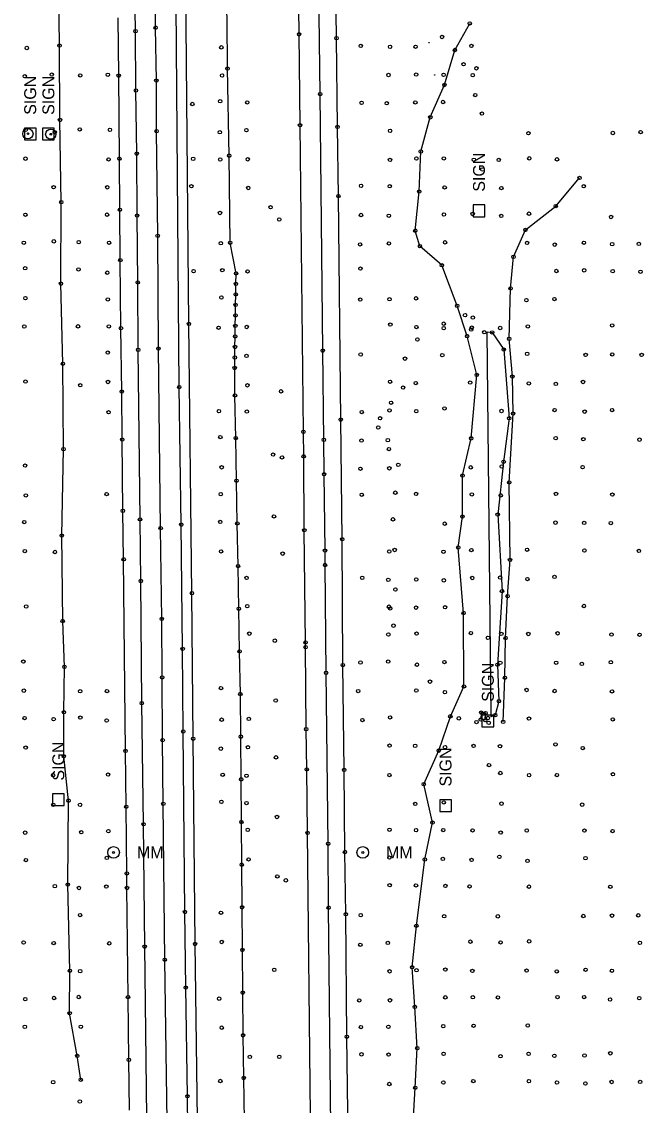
# Model space of a CAD drawing. Extents: x 20503438 to 20508873, y 7964251 to 7984667.
# Drawn here: x 20505333 to 20505698, y 7979935 to 7980570 of the extents above; entities that cross this region are included whole.
import ezdxf

# ---------------------------------------------------------------- set-up
doc = ezdxf.new("R2010")
doc.units = 0
for name, color, linetype in [('SurBreakLine', 7, 'Continuous'), ('SurControl', 7, 'Continuous'), ('SurDrainageArrowDown', 7, 'Continuous'), ('SurEdgeRoadPaved', 7, 'Continuous'), ('SurEdgeShoulderPaved', 7, 'Continuous'), ('SurMiscStructureLine', 7, 'Continuous'), ('SurPointsNonDTM', 7, 'Continuous'), ('SurRoadPoints', 7, 'Continuous'), ('SurSurveyPoints', 7, 'Continuous'), ('SurTreeLineLeft', 7, 'Continuous')]:
    doc.layers.add(name, color=color, linetype=linetype)

msp = doc.modelspace()

# ---------------------------------------------------------------- linework, layer by layer
at = {"layer": 'SurBreakLine'}
for points in [[(20505502.82, 7979928.73), (20505501.16, 7980094.42), (20505500.7, 7980131.63), (20505500.35, 7980155.21), (20505500.03, 7980203.28), (20505500, 7980206.06), (20505499.27, 7980271.76), (20505498.89, 7980315.07), (20505498.72, 7980329.42), (20505496.74, 7980509.09), (20505496.18, 7980562.37), (20505495.83, 7980592.98), (20505495.56, 7980624.79), (20505494.56, 7980715.32), (20505494.07, 7980758.55), (20505493.65, 7980795.75), (20505493.28, 7980832.76), (20505492.74, 7980874.49), (20505492.33, 7980901.35), (20505491.27, 7980994.69)], [(20505418.93, 7979912.11), (20505417.39, 7980020.09), (20505416.54, 7980111.44), (20505416.16, 7980148.77), (20505415.87, 7980185.54), (20505415.61, 7980219.83), (20505414.98, 7980273.06), (20505413.7, 7980378.2), (20505413.25, 7980444.28), (20505412.62, 7980505.63), (20505412.46, 7980535.27), (20505412.01, 7980566.27), (20505411.1, 7980668.83), (20505409.87, 7980764.66), (20505409.52, 7980790.7), (20505409.02, 7980836.41), (20505408.56, 7980861.54), (20505408.11, 7980905.42), (20505407.63, 7980936.71)], [(20505615.91, 7980159.52), (20505616.95, 7980185.34), (20505617.35, 7980208.62), (20505618.51, 7980233.14), (20505619.93, 7980254.39), (20505619.47, 7980299.79), (20505621.75, 7980340.13), (20505621.29, 7980361.79), (20505619.43, 7980383.94), (20505620.25, 7980413.47), (20505621.95, 7980432), (20505628.98, 7980447.77), (20505646.74, 7980461.72), (20505660.76, 7980478.21)]]:
    msp.add_lwpolyline(points, dxfattribs=at)
at = {"layer": 'SurControl'}
for centre in [(20505572.47, 7980557.49), (20505575.81, 7980538.5)]:
    msp.add_circle(centre, 0.15, dxfattribs=at)
at = {"layer": 'SurDrainageArrowDown'}
for points in [[(20505455.75, 7980440.25), (20505455.16, 7980491.26), (20505454.21, 7980542.27), (20505454.01, 7980570.91), (20505453.19, 7980592.26), (20505451.34, 7980609.26), (20505446.96, 7980613.69), (20505442.6, 7980613.8)], [(20505368.13, 7979949.77), (20505366.04, 7979963.72), (20505361.61, 7979988.72), (20505361.78, 7980013.67), (20505360.5, 7980064.12), (20505360.95, 7980113.29), (20505358.15, 7980139.35), (20505358.26, 7980165.11), (20505358.56, 7980191.72), (20505357.53, 7980218.57), (20505356.98, 7980268.66), (20505358, 7980319.29), (20505357.64, 7980369.33), (20505356.48, 7980416.28), (20505356.69, 7980464.03), (20505355.94, 7980512.18), (20505355.65, 7980555.76), (20505355.07, 7980601.84)], [(20505563.12, 7979924.54), (20505564.34, 7979945.1), (20505565.51, 7979968.29), (20505564.11, 7979992.43), (20505562.47, 7980015.69), (20505564.99, 7980040.01), (20505569.98, 7980078.85), (20505574.44, 7980100.46), (20505569.31, 7980122.96), (20505578.13, 7980142.63), (20505584.92, 7980162.71), (20505592.92, 7980180.26), (20505592.67, 7980223.26), (20505589.56, 7980261.64), (20505591.98, 7980279.78), (20505592.04, 7980303.79), (20505597.14, 7980325.64), (20505600.42, 7980362.8), (20505594.74, 7980385.49), (20505588.92, 7980403.27), (20505579.92, 7980427.03), (20505567.05, 7980438.23), (20505564.34, 7980447.3), (20505566.67, 7980470.22), (20505567.62, 7980493.73), (20505573.17, 7980513.73), (20505581.44, 7980532.68), (20505587.62, 7980553.18), (20505596.29, 7980568.74)], [(20505464.1, 7979925.82), (20505463.72, 7979950.81), (20505463.34, 7979975.81), (20505463.14, 7980000.81), (20505462.95, 7980025.81), (20505462.77, 7980050.81), (20505462.58, 7980075.8), (20505462.39, 7980100.8), (20505462.2, 7980125.8), (20505462.01, 7980150.8), (20505461.74, 7980175.8), (20505461.29, 7980200.79), (20505460.85, 7980225.79), (20505460.4, 7980250.79), (20505459.95, 7980275.78), (20505459.5, 7980300.78), (20505459.05, 7980325.77), (20505458.6, 7980350.77), (20505458.41, 7980366.85), (20505458.5, 7980373.01), (20505458.6, 7980379.17), (20505458.69, 7980385.33), (20505458.78, 7980391.49), (20505458.88, 7980397.65), (20505458.97, 7980403.81), (20505459.06, 7980409.97), (20505459.16, 7980416.13), (20505459.25, 7980422.29), (20505455.75, 7980440.25)]]:
    msp.add_lwpolyline(points, dxfattribs=at)
at = {"layer": 'SurEdgeRoadPaved'}
for points in [[(20505407.01, 7979911.27), (20505405.62, 7980027.77), (20505404.97, 7980099.48), (20505403.88, 7980170.44), (20505403.36, 7980242.05), (20505402.88, 7980278.12), (20505401.81, 7980377.51), (20505401.55, 7980417.01), (20505401.15, 7980456.16), (20505400.97, 7980492.44), (20505400.5, 7980529.47), (20505400.23, 7980564.23), (20505399.63, 7980600.95), (20505398.46, 7980703.6), (20505397.89, 7980772.13), (20505396.33, 7980909.55), (20505395.68, 7980987.14)], [(20505433.05, 7979713.21), (20505430.71, 7979940.08), (20505429.71, 7980003.79), (20505429.2, 7980048.09), (20505428.22, 7980153.85), (20505427.89, 7980202.23), (20505427.07, 7980275.05), (20505425.92, 7980355.65), (20505424.11, 7980579.66), (20505423.37, 7980648.54), (20505420.77, 7980848.98), (20505419.47, 7980988.86)], [(20505516.05, 7979812.06), (20505513.49, 7980050.6), (20505513.24, 7980088.09), (20505512.01, 7980188.2), (20505511.47, 7980251.39), (20505511.41, 7980259.84), (20505510.87, 7980304.58), (20505510.69, 7980324.76), (20505510.08, 7980377.01), (20505508.54, 7980527.34), (20505507.19, 7980635.55), (20505506.92, 7980663.36), (20505505.94, 7980736.75), (20505505.07, 7980842.4), (20505504.2, 7980911.75), (20505503.99, 7980947.26)]]:
    msp.add_lwpolyline(points, dxfattribs=at)
at = {"layer": 'SurEdgeShoulderPaved'}
for points in [[(20505436.58, 7979926.47), (20505435.19, 7980029.33), (20505434.04, 7980149.6), (20505433.33, 7980234.89), (20505431.57, 7980392.66), (20505429.57, 7980611.85), (20505428.94, 7980656.15), (20505428.39, 7980719.4), (20505428.03, 7980745.3), (20505427.42, 7980798.3), (20505426.86, 7980832.89), (20505425.41, 7980977.21)], [(20505525.14, 7979901.72), (20505524.22, 7979974.98), (20505523.61, 7980046.77), (20505523.09, 7980083.23), (20505522.65, 7980131.31), (20505521.87, 7980192.78), (20505521.53, 7980266.52), (20505520.61, 7980336.57), (20505519.29, 7980467.56), (20505518.75, 7980508.1), (20505518.14, 7980560.14), (20505516.98, 7980650.97), (20505516.82, 7980662.74), (20505516.06, 7980714.7), (20505516.27, 7980750.94), (20505515.28, 7980821.55), (20505514.45, 7980923.25)], [(20505396.63, 7979932.02), (20505396.34, 7979961.46), (20505395.84, 7979998.23), (20505395.23, 7980062.14), (20505395.14, 7980070.7), (20505394.81, 7980109.76), (20505394.37, 7980142.46), (20505393.29, 7980254.72), (20505392.82, 7980283.13), (20505392.48, 7980324.91), (20505392.19, 7980353.04), (20505391.71, 7980390.19), (20505391.32, 7980430.1), (20505391.07, 7980459.58), (20505390.82, 7980489.5), (20505390.37, 7980538.15), (20505390.02, 7980571.99)]]:
    msp.add_lwpolyline(points, dxfattribs=at)
at = {"layer": 'SurMiscStructureLine'}
msp.add_lwpolyline([(20505605.38, 7980160.44), (20505605.6, 7980164.63), (20505603.07, 7980164.89), (20505602.78, 7980160.83)], dxfattribs=at)
at = {"layer": 'SurPointsNonDTM'}
for centre in [(20505580.1, 7980560.82), (20505592.68, 7980544.84), (20505600.24, 7980542.46), (20505599.51, 7980526.77), (20505603.43, 7980515.91), (20505603.79, 7980483.17), (20505593.54, 7980397.78), (20505598.1, 7980396.41), (20505581.03, 7980392.8), (20505597.15, 7980389.37), (20505604.79, 7980387.78), (20505609.45, 7980387.7), (20505565.6, 7980383.55), (20505616.27, 7980377.63), (20505558.33, 7980372.32), (20505557.19, 7980355.39), (20505550.18, 7980346.48), (20505543.69, 7980337.38), (20505619.45, 7980337.41), (20505542.61, 7980331.98), (20505548.89, 7980319.31), (20505616.2, 7980311.84), (20505554.41, 7980310.1), (20505552.66, 7980293.77), (20505612.7, 7980280.94), (20505551.3, 7980278.15), (20505552.26, 7980260.2), (20505552.68, 7980237.07), (20505615.23, 7980236.14), (20505549.6, 7980225.94), (20505551.6, 7980215.87), (20505607.01, 7980208.72), (20505612.56, 7980192.97), (20505573.01, 7980183.05), (20505613.39, 7980171.62), (20505589.91, 7980161.55), (20505600.28, 7980159.35), (20505602.78, 7980160.83), (20505603.07, 7980164.89), (20505605.38, 7980160.44), (20505605.6, 7980164.63), (20505606.97, 7980161.77), (20505607.42, 7980158.94), (20505611.29, 7980163.4), (20505607.59, 7980134.15)]:
    msp.add_circle(centre, 1, dxfattribs=at)
at = {"layer": 'SurRoadPoints'}
for points in [[(20505341.89, 7980504.01), (20505341.89, 7980504.01), (20505341.89, 7980507.44), (20505335.03, 7980507.44), (20505335.03, 7980500.58), (20505341.89, 7980500.58), (20505341.89, 7980504.01)], [(20505352.56, 7980503.98), (20505352.56, 7980503.98), (20505352.56, 7980507.41), (20505345.7, 7980507.41), (20505345.7, 7980500.55), (20505352.56, 7980500.55), (20505352.56, 7980503.98)], [(20505605.15, 7980458.95), (20505605.15, 7980458.95), (20505605.15, 7980462.38), (20505598.29, 7980462.38), (20505598.29, 7980455.52), (20505605.15, 7980455.52), (20505605.15, 7980458.95)], [(20505610.35, 7980160.03), (20505610.35, 7980160.03), (20505610.35, 7980163.46), (20505603.49, 7980163.46), (20505603.49, 7980156.6), (20505610.35, 7980156.6), (20505610.35, 7980160.03)], [(20505358.36, 7980113.85), (20505358.36, 7980113.85), (20505358.36, 7980117.28), (20505351.5, 7980117.28), (20505351.5, 7980110.42), (20505358.36, 7980110.42), (20505358.36, 7980113.85)], [(20505585.53, 7980110.41), (20505585.53, 7980110.41), (20505585.53, 7980113.84), (20505578.67, 7980113.84), (20505578.67, 7980106.98), (20505585.53, 7980106.98), (20505585.53, 7980110.41)]]:
    msp.add_lwpolyline(points, dxfattribs=at)
for centre, radius in [((20505337.14, 7980504.13), 3), ((20505337.14, 7980504.13), 0.5), ((20505350.53, 7980503.85), 3), ((20505350.53, 7980503.85), 0.5), ((20505387.38, 7980082.96), 3.43), ((20505533.54, 7980082.96), 3.43), ((20505387.38, 7980082.96), 0.571), ((20505533.54, 7980082.96), 0.571)]:
    msp.add_circle(centre, radius, dxfattribs=at)
at = {"layer": 'SurSurveyPoints'}
for centre in [(20505412.01, 7980566.27), (20505596.29, 7980568.74), (20505400.23, 7980564.23), (20505496.18, 7980562.37), (20505518.14, 7980560.14), (20505336.48, 7980554.35), (20505355.65, 7980555.76), (20505450.58, 7980554.74), (20505532.34, 7980555.56), (20505549.57, 7980555.04), (20505564.55, 7980555.08), (20505587.62, 7980553.18), (20505597.26, 7980555.6), (20505454.21, 7980542.27), (20505335.25, 7980537.8), (20505351.09, 7980538.79), (20505367.81, 7980538.31), (20505384.02, 7980538.69), (20505390.37, 7980538.15), (20505412.46, 7980535.27), (20505451, 7980538.26), (20505548.63, 7980538.55), (20505564.88, 7980538.76), (20505580.97, 7980538.63), (20505598.05, 7980538.44), (20505400.5, 7980529.47), (20505508.54, 7980527.34), (20505581.44, 7980532.68), (20505433.56, 7980521.53), (20505449.89, 7980523.15), (20505465.78, 7980522.45), (20505532.87, 7980522.21), (20505547.64, 7980522), (20505564.37, 7980522.48), (20505580.66, 7980522.71), (20505355.94, 7980512.18), (20505496.74, 7980509.09), (20505518.75, 7980508.1), (20505573.17, 7980513.73), (20505335.79, 7980506.4), (20505352.85, 7980505), (20505367.53, 7980506.65), (20505385.21, 7980506.42), (20505412.62, 7980505.63), (20505449.71, 7980505.01), (20505465.32, 7980506.19), (20505549.59, 7980505.81), (20505630.74, 7980504.4), (20505680.24, 7980504.54), (20505696.56, 7980505.09), (20505335.69, 7980489.49), (20505384.44, 7980489.07), (20505390.82, 7980489.5), (20505400.97, 7980492.44), (20505434.05, 7980489.41), (20505449.95, 7980489), (20505455.16, 7980491.26), (20505466.09, 7980489.14), (20505565.03, 7980489.61), (20505567.62, 7980493.73), (20505581.1, 7980489.65), (20505631.22, 7980489.7), (20505647.5, 7980489.11), (20505549.53, 7980488.75), (20505598.7, 7980488.87), (20505613.3, 7980488.75), (20505660.76, 7980478.21), (20505352.22, 7980472.74), (20505383.65, 7980472.71), (20505432.99, 7980473.36), (20505466.37, 7980472.33), (20505532.58, 7980473.57), (20505549.39, 7980473.37), (20505566.67, 7980470.22), (20505581.58, 7980472.68), (20505614.84, 7980472.29), (20505663.16, 7980473.32), (20505356.69, 7980464.03), (20505519.29, 7980467.56), (20505391.07, 7980459.58), (20505449.81, 7980457.67), (20505479.47, 7980461.05), (20505631.04, 7980457.27), (20505646.74, 7980461.72), (20505335.65, 7980456.62), (20505383.56, 7980456.69), (20505401.15, 7980456.16), (20505484.57, 7980453.84), (20505532.51, 7980456.48), (20505548.82, 7980456.06), (20505581.16, 7980456.77), (20505598.03, 7980457.1), (20505614.81, 7980455.98), (20505679.2, 7980455.34), (20505564.34, 7980447.3), (20505628.98, 7980447.77), (20505334.75, 7980440.25), (20505352.31, 7980441.06), (20505366.96, 7980440.56), (20505384.72, 7980440.23), (20505413.25, 7980444.28), (20505450.28, 7980439.95), (20505455.75, 7980440.25), (20505455.75, 7980440.25), (20505531.99, 7980439.26), (20505548.9, 7980439.85), (20505567.05, 7980438.23), (20505581.82, 7980440.47), (20505629.93, 7980440.16), (20505646.19, 7980439.13), (20505663.3, 7980440.25), (20505679.87, 7980439.42), (20505695.5, 7980439.56), (20505621.95, 7980432), (20505391.32, 7980430.1), (20505579.92, 7980427.03), (20505335.53, 7980425.28), (20505366.78, 7980424.63), (20505383.67, 7980422.7), (20505434.33, 7980423.59), (20505451.16, 7980424.13), (20505459.25, 7980422.29), (20505465.97, 7980423.44), (20505532.18, 7980425.11), (20505647.15, 7980423.67), (20505663.4, 7980424.08), (20505680.15, 7980423.6), (20505696.47, 7980423.26), (20505356.48, 7980416.28), (20505401.55, 7980417.01), (20505459.16, 7980416.13), (20505620.25, 7980413.47), (20505335.66, 7980407.75), (20505383.99, 7980407.02), (20505450.62, 7980408.17), (20505459.06, 7980409.97), (20505532.05, 7980406.95), (20505549.21, 7980407.13), (20505564.85, 7980407.66), (20505629.52, 7980406.59), (20505645.98, 7980407.21), (20505458.97, 7980403.81), (20505588.92, 7980403.27), (20505458.88, 7980397.65), (20505335.01, 7980391.16), (20505366.49, 7980391.25), (20505384.6, 7980391.2), (20505391.71, 7980390.19), (20505431.57, 7980392.66), (20505448.96, 7980390.45), (20505458.78, 7980391.49), (20505465.5, 7980390.88), (20505549.7, 7980392.3), (20505565.02, 7980390.83), (20505581.05, 7980390.18), (20505597.47, 7980390.5), (20505614.15, 7980390.28), (20505630.39, 7980391.22), (20505679.86, 7980391.79), (20505458.69, 7980385.33), (20505594.74, 7980385.49), (20505619.43, 7980383.94), (20505383.96, 7980375.89), (20505401.81, 7980377.51), (20505413.7, 7980378.2), (20505458.6, 7980379.17), (20505510.08, 7980377.01), (20505532.33, 7980374.77), (20505629.98, 7980375.14), (20505679.88, 7980374.8), (20505357.64, 7980369.33), (20505458.5, 7980373.01), (20505465.36, 7980373.93), (20505580.21, 7980374.34), (20505664.29, 7980374.5), (20505697.14, 7980374.49), (20505458.41, 7980366.85), (20505600.42, 7980362.8), (20505335.71, 7980358.88), (20505367.82, 7980356.71), (20505384.11, 7980358.65), (20505425.92, 7980355.65), (20505465.91, 7980356.69), (20505549.59, 7980358.77), (20505564.62, 7980358), (20505596.54, 7980358.32), (20505621.29, 7980361.79), (20505630.95, 7980357.79), (20505646.81, 7980357.52), (20505662.72, 7980358.65), (20505392.19, 7980353.04), (20505458.6, 7980350.77), (20505485.64, 7980353.16), (20505581.48, 7980343.14), (20505384.43, 7980340.93), (20505449.18, 7980341.55), (20505465.53, 7980341.32), (20505520.61, 7980336.57), (20505532.96, 7980341), (20505549.25, 7980342), (20505564.92, 7980341.55), (20505614.92, 7980341.66), (20505621.75, 7980340.13), (20505646.09, 7980342.17), (20505663.72, 7980341.27), (20505679.78, 7980342.2), (20505392.48, 7980324.91), (20505449.99, 7980326.35), (20505459.05, 7980325.77), (20505498.72, 7980329.42), (20505510.69, 7980324.76), (20505532.82, 7980324.32), (20505548.24, 7980324.56), (20505597.14, 7980325.64), (20505646.72, 7980325.71), (20505662.92, 7980325.11), (20505695.88, 7980324.86), (20505358, 7980319.29), (20505480.94, 7980316.13), (20505486.19, 7980314.44), (20505498.89, 7980315.07), (20505335.45, 7980309.64), (20505450.78, 7980308.65), (20505532.15, 7980307.82), (20505549.15, 7980308.07), (20505596.88, 7980308.63), (20505615.09, 7980309.12), (20505662.51, 7980308.75), (20505459.5, 7980300.78), (20505510.87, 7980304.58), (20505592.04, 7980303.79), (20505619.47, 7980299.79), (20505335.9, 7980292.17), (20505383.32, 7980292.97), (20505450.24, 7980292.9), (20505532.93, 7980292.55), (20505564.81, 7980293.04), (20505597.55, 7980292.75), (20505614.51, 7980292.22), (20505646.88, 7980293.08), (20505679.96, 7980292.68), (20505392.82, 7980283.13), (20505481.47, 7980279.89), (20505591.98, 7980279.78), (20505334.99, 7980276.53), (20505402.88, 7980278.12), (20505427.07, 7980275.05), (20505449.94, 7980276.66), (20505459.95, 7980275.78), (20505581.66, 7980275.62), (20505646.61, 7980276.22), (20505663.4, 7980276.06), (20505679.08, 7980275.97), (20505356.98, 7980268.66), (20505414.98, 7980273.06), (20505499.27, 7980271.76), (20505521.53, 7980266.52), (20505589.56, 7980261.64), (20505335.34, 7980259.54), (20505352.95, 7980259.01), (20505393.29, 7980254.72), (20505450.44, 7980259.39), (20505486.58, 7980258.06), (20505511.41, 7980259.84), (20505549.11, 7980259.3), (20505580.91, 7980259.15), (20505597.24, 7980260.15), (20505619.93, 7980254.39), (20505629.92, 7980260.36), (20505663.55, 7980259.91), (20505695.53, 7980259.64), (20505460.4, 7980250.79), (20505511.47, 7980251.39), (20505403.36, 7980242.05), (20505465.39, 7980243.85), (20505533.26, 7980243.88), (20505548.54, 7980242.73), (20505564.93, 7980242.91), (20505581.11, 7980242.44), (20505597.75, 7980243.8), (20505614.12, 7980244.02), (20505630.15, 7980243.14), (20505646.01, 7980244.44), (20505433.33, 7980234.89), (20505618.51, 7980233.14), (20505336.12, 7980227.07), (20505460.85, 7980225.79), (20505465.78, 7980227.29), (20505548.94, 7980226.97), (20505564.81, 7980226.42), (20505581.83, 7980226.65), (20505592.67, 7980223.26), (20505663.25, 7980227.37), (20505357.53, 7980218.57), (20505415.61, 7980219.83), (20505467, 7980211.19), (20505548.55, 7980210.66), (20505565.11, 7980211.22), (20505597.01, 7980211.51), (20505614.83, 7980211.02), (20505630.67, 7980210.98), (20505647.83, 7980211.37), (20505679.44, 7980210.65), (20505695.91, 7980210.53), (20505481.99, 7980207.06), (20505500, 7980206.06), (20505500.03, 7980203.28), (20505617.35, 7980208.62), (20505427.89, 7980202.23), (20505461.29, 7980200.79), (20505334.45, 7980194.82), (20505358.56, 7980191.72), (20505521.87, 7980192.78), (20505532.2, 7980194.25), (20505548.43, 7980194.8), (20505565.31, 7980192.99), (20505581.47, 7980194.5), (20505614.24, 7980194.08), (20505647, 7980194.11), (20505662.06, 7980193.44), (20505679.07, 7980194.42), (20505415.87, 7980185.54), (20505512.01, 7980188.2), (20505616.95, 7980185.34), (20505450.38, 7980179.3), (20505564.95, 7980177.86), (20505592.92, 7980180.26), (20505629.67, 7980178.16), (20505334.73, 7980177.77), (20505367.76, 7980177.42), (20505383.5, 7980177.54), (20505461.74, 7980175.8), (20505482.46, 7980171.99), (20505530.83, 7980177.53), (20505581.76, 7980176.91), (20505646.06, 7980177.57), (20505679.76, 7980177.34), (20505403.88, 7980170.44), (20505335.16, 7980161.69), (20505352.22, 7980161.08), (20505358.26, 7980165.11), (20505367.87, 7980162), (20505383.32, 7980160.3), (20505450.76, 7980160.77), (20505466.72, 7980161.22), (20505533.35, 7980160.51), (20505549.55, 7980162.11), (20505584.92, 7980162.71), (20505615.91, 7980159.52), (20505631.04, 7980161.4), (20505680.17, 7980160.93), (20505428.22, 7980153.85), (20505500.35, 7980155.21), (20505416.16, 7980148.77), (20505434.04, 7980149.6), (20505462.01, 7980150.8), (20505646.62, 7980146.27), (20505335.81, 7980144.4), (20505394.37, 7980142.46), (20505450.31, 7980143.79), (20505466.17, 7980144.59), (20505549.28, 7980145.57), (20505564.31, 7980145.42), (20505578.13, 7980142.63), (20505581.79, 7980144.64), (20505598.53, 7980145.39), (20505614.06, 7980145.22), (20505662.61, 7980144.14), (20505358.15, 7980139.35), (20505482.64, 7980138.7), (20505351.9, 7980128.26), (20505384.15, 7980128.57), (20505451.37, 7980128.51), (20505465.35, 7980127.93), (20505500.7, 7980131.63), (20505522.65, 7980131.31), (20505549.16, 7980128.32), (20505614.24, 7980129.52), (20505631.11, 7980128.24), (20505647.44, 7980128.31), (20505680.28, 7980128.8), (20505462.2, 7980125.8), (20505569.31, 7980122.96), (20505351.97, 7980110.88), (20505360.95, 7980113.29), (20505367.69, 7980110.86), (20505394.81, 7980109.76), (20505416.54, 7980111.44), (20505450.61, 7980112.62), (20505465.34, 7980111.88), (20505564.33, 7980111.43), (20505581.04, 7980112.31), (20505614.93, 7980111.56), (20505662.27, 7980110.97), (20505483.24, 7980103.76), (20505384.32, 7980095.45), (20505404.97, 7980099.48), (20505462.39, 7980100.8), (20505466.08, 7980096.2), (20505549.21, 7980096.26), (20505564.83, 7980096.01), (20505574.44, 7980100.46), (20505580.75, 7980096.08), (20505597.97, 7980095.86), (20505629.73, 7980095.84), (20505663.59, 7980095.79), (20505680.08, 7980095.48), (20505335.5, 7980094.56), (20505368.4, 7980094.82), (20505501.16, 7980094.42), (20505614.45, 7980094.6), (20505513.24, 7980088.09), (20505523.09, 7980083.23), (20505335.93, 7980078.5), (20505383.44, 7980079.78), (20505466.59, 7980078.89), (20505549.2, 7980079.94), (20505569.98, 7980078.85), (20505580.52, 7980079.18), (20505597.4, 7980078.57), (20505613.68, 7980080.39), (20505630.16, 7980077.98), (20505664.19, 7980079.63), (20505395.14, 7980070.7), (20505462.58, 7980075.8), (20505360.5, 7980064.12), (20505483.42, 7980068.91), (20505488.42, 7980066.61), (20505549.33, 7980063.76), (20505564.76, 7980063.64), (20505352.93, 7980063.2), (20505367.02, 7980062.14), (20505383.11, 7980062.98), (20505395.23, 7980062.14), (20505582.04, 7980063.36), (20505596.19, 7980063.06), (20505630.99, 7980062.91), (20505678.75, 7980062.85), (20505367.72, 7980046.26), (20505429.2, 7980048.09), (20505450.38, 7980047.61), (20505462.77, 7980050.81), (20505513.49, 7980050.6), (20505523.61, 7980046.77), (20505532.36, 7980046.22), (20505581.28, 7980045.56), (20505612.76, 7980045.52), (20505662.92, 7980045.71), (20505679.73, 7980045.93), (20505695.17, 7980046.1), (20505564.99, 7980040.01), (20505334.62, 7980030.18), (20505352.25, 7980029.87), (20505384.82, 7980029.69), (20505405.62, 7980027.77), (20505435.19, 7980029.33), (20505450.81, 7980030.5), (20505462.95, 7980025.81), (20505532.1, 7980028.89), (20505548.27, 7980029.93), (20505596.7, 7980030.68), (20505614.41, 7980030.25), (20505631.17, 7980030.86), (20505696.15, 7980029.99), (20505417.39, 7980020.09), (20505361.78, 7980013.67), (20505367.78, 7980013.4), (20505481.63, 7980014.16), (20505549.3, 7980013.31), (20505562.47, 7980015.69), (20505565.09, 7980013.96), (20505581.99, 7980014.32), (20505597.84, 7980013.53), (20505629.66, 7980013.74), (20505647.33, 7980013.26), (20505664.25, 7980014.22), (20505679.69, 7980013.64), (20505429.71, 7980003.79), (20505463.14, 7980000.81), (20505335.55, 7979996.98), (20505352.46, 7979997.67), (20505366.95, 7979998.25), (20505395.84, 7979998.23), (20505449.33, 7979997.28), (20505531.51, 7979996.25), (20505549.53, 7979996.32), (20505581.97, 7979998.05), (20505598.11, 7979998.14), (20505612.84, 7979998.03), (20505647.8, 7979998.23), (20505663.39, 7979998.21), (20505678.63, 7979996.81), (20505695.74, 7979997.56), (20505361.61, 7979988.72), (20505564.11, 7979992.43), (20505580.76, 7979981.17), (20505598.55, 7979981.4), (20505630.33, 7979981.56), (20505335.33, 7979980.77), (20505368.18, 7979980.84), (20505450.85, 7979980.29), (20505463.34, 7979975.81), (20505524.22, 7979974.98), (20505532.44, 7979980.62), (20505548.56, 7979980.8), (20505565.51, 7979968.29), (20505366.04, 7979963.72), (20505467.3, 7979963.17), (20505484.55, 7979963.18), (20505532.81, 7979964.67), (20505548.68, 7979964.52), (20505580.94, 7979964.97), (20505614.36, 7979963.52), (20505630.83, 7979964.98), (20505645.93, 7979963.78), (20505663.62, 7979963.99), (20505678.75, 7979965.27), (20505396.34, 7979961.46), (20505368.13, 7979949.77), (20505463.72, 7979950.81), (20505351.96, 7979948.36), (20505450, 7979949.04), (20505549.15, 7979947.28), (20505564.34, 7979945.1), (20505580.81, 7979948.16), (20505598.4, 7979948.98), (20505631, 7979948.95), (20505647.48, 7979948.14), (20505664.13, 7979947.59), (20505679.49, 7979948.46), (20505696.26, 7979948.5), (20505367.58, 7979937.05), (20505430.71, 7979940.08)]:
    msp.add_circle(centre, 1, dxfattribs=at)
at = {"layer": 'SurTreeLineLeft'}
msp.add_lwpolyline([(20505611.29, 7980163.4), (20505608.87, 7980162.51), (20505606.56, 7980388.09), (20505609.45, 7980387.7), (20505616.27, 7980377.63), (20505619.45, 7980337.41), (20505616.2, 7980311.84), (20505612.7, 7980280.94), (20505615.23, 7980236.14), (20505612.56, 7980192.97), (20505613.39, 7980171.62), (20505611.29, 7980163.4)], dxfattribs=at)

# ---------------------------------------------------------------- texts
at = {"layer": 'SurRoadPoints'}
for s, rotation, p in [('SIGN', 90, (20505341.96, 7980515.22)), ('SIGN', 90, (20505352.63, 7980515.19)), ('SIGN', 90, (20505605.22, 7980470.16)), ('SIGN', 90, (20505610.42, 7980171.24)), ('SIGN', 90, (20505358.43, 7980125.06)), ('SIGN', 90, (20505585.6, 7980121.62)), ('MM', 360, (20505401.09, 7980079.46)), ('MM', 360, (20505547.25, 7980079.46))]:
    msp.add_text(s, height=6.995, rotation=rotation, dxfattribs=at).set_placement(p)

doc.saveas('drawing.dxf')
